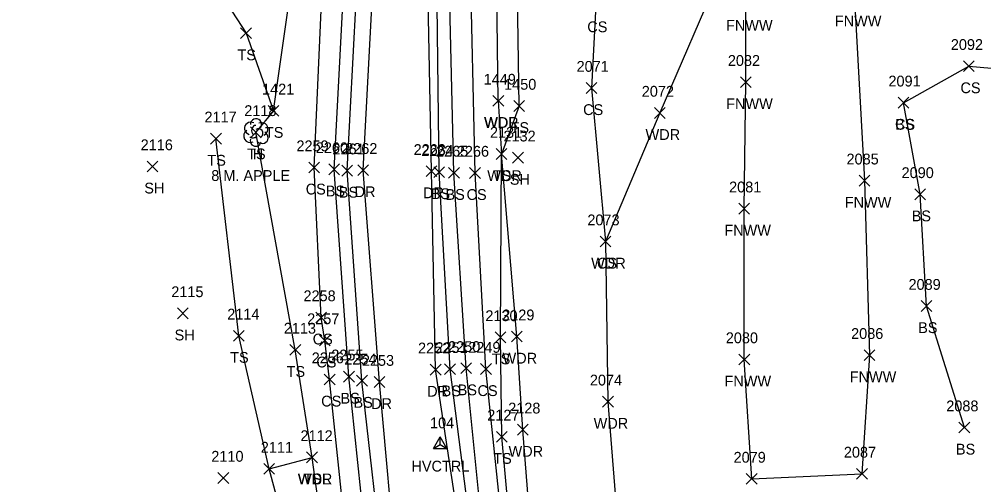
# Model space of a CAD drawing. Extents: x 1761340 to 1763889, y 696770 to 706023.
# Drawn here: x 1761583.4 to 1761761.6, y 700663 to 700749.1 of the extents above; entities that cross this region are included whole.
import ezdxf

# ---------------------------------------------------------------- set-up
doc = ezdxf.new("R2010")
doc.units = 0
for name, color, linetype in [('C_A', 7, 'Continuous'), ('C_I', 7, 'Continuous'), ('CPSM', 7, 'Continuous'), ('L_A', 7, 'Continuous'), ('L_C', 7, 'Continuous'), ('L_I', 7, 'Continuous'), ('L_TIC', 7, 'Continuous'), ('LAWA', 7, 'Continuous'), ('LELB', 7, 'Continuous'), ('LFNC', 7, 'Continuous'), ('LTD', 7, 'Continuous'), ('R_A', 7, 'Continuous'), ('R_I', 7, 'Continuous'), ('R_TIC', 7, 'Continuous'), ('RDP', 7, 'Continuous')]:
    doc.layers.add(name, color=color, linetype=linetype)

msp = doc.modelspace()

# ---------------------------------------------------------------- linework, layer by layer
at = {"layer": 'CPSM'}
for p, q in [((1761659.89, 700669.75), (1761661.14, 700671.91)), ((1761662.39, 700669.75), (1761661.14, 700671.91)), ((1761661.14, 700670.47), (1761661.14, 700671.91)), ((1761659.89, 700669.75), (1761661.14, 700670.47)), ((1761659.89, 700669.75), (1761662.39, 700669.75)), ((1761661.14, 700670.47), (1761661.14, 700670.47)), ((1761661.14, 700670.47), (1761662.39, 700669.75))]:
    msp.add_line(p, q, dxfattribs=at)
at = {"layer": 'L_TIC'}
for points in [[(1761624.27, 700745.55), (1761626.27, 700747.55)], [(1761626.27, 700745.55), (1761624.27, 700747.55)], [(1761757.85, 700739.46), (1761759.85, 700741.46)], [(1761759.85, 700739.46), (1761757.85, 700741.46)], [(1761716.65, 700736.51), (1761718.65, 700738.51)], [(1761718.65, 700736.51), (1761716.65, 700738.51)], [(1761688.12, 700735.42), (1761690.12, 700737.42)], [(1761690.12, 700735.42), (1761688.12, 700737.42)], [(1761670.88, 700733.04), (1761672.88, 700735.04)], [(1761672.88, 700733.04), (1761670.88, 700735.04)], [(1761670.88, 700733.04), (1761672.88, 700735.04)], [(1761672.88, 700733.04), (1761670.88, 700735.04)], [(1761629.34, 700731.21), (1761631.34, 700733.21)], [(1761631.34, 700731.21), (1761629.34, 700733.21)], [(1761674.74, 700732.1), (1761676.74, 700734.1)], [(1761676.74, 700732.1), (1761674.74, 700734.1)], [(1761745.76, 700732.7), (1761747.76, 700734.7)], [(1761747.76, 700732.7), (1761745.76, 700734.7)], [(1761745.76, 700732.7), (1761747.76, 700734.7)], [(1761747.76, 700732.7), (1761745.76, 700734.7)], [(1761700.74, 700730.81), (1761702.74, 700732.81)], [(1761702.74, 700730.81), (1761700.74, 700732.81)], [(1761618.71, 700726.05), (1761620.71, 700728.05)], [(1761620.71, 700726.05), (1761618.71, 700728.05)], [(1761626.06, 700727.23), (1761628.06, 700729.23)], [(1761628.06, 700727.23), (1761626.06, 700729.23)], [(1761671.48, 700723.21), (1761673.48, 700725.21)], [(1761673.48, 700723.21), (1761671.48, 700725.21)], [(1761671.48, 700723.21), (1761673.48, 700725.21)], [(1761673.48, 700723.21), (1761671.48, 700725.21)], [(1761674.53, 700722.53), (1761676.53, 700724.53)], [(1761676.53, 700722.53), (1761674.53, 700724.53)], [(1761606.97, 700720.91), (1761608.97, 700722.91)], [(1761608.97, 700720.91), (1761606.97, 700722.91)], [(1761636.85, 700720.72), (1761638.85, 700722.72)], [(1761638.85, 700720.72), (1761636.85, 700722.72)], [(1761640.56, 700720.37), (1761642.56, 700722.37)], [(1761642.56, 700720.37), (1761640.56, 700722.37)], [(1761642.97, 700720.14), (1761644.97, 700722.14)], [(1761644.97, 700720.14), (1761642.97, 700722.14)], [(1761659.97, 700719.86), (1761661.97, 700721.86)], [(1761661.97, 700719.86), (1761659.97, 700721.86)], [(1761662.69, 700719.73), (1761664.69, 700721.73)], [(1761664.69, 700719.73), (1761662.69, 700721.73)], [(1761666.58, 700719.71), (1761668.58, 700721.71)], [(1761668.58, 700719.71), (1761666.58, 700721.71)], [(1761738.58, 700718.28), (1761740.58, 700720.28)], [(1761740.58, 700718.28), (1761738.58, 700720.28)], [(1761748.84, 700715.76), (1761750.84, 700717.76)], [(1761750.84, 700715.76), (1761748.84, 700717.76)], [(1761716.32, 700713.11), (1761718.32, 700715.11)], [(1761718.32, 700713.11), (1761716.32, 700715.11)], [(1761690.69, 700707.02), (1761692.69, 700709.02)], [(1761692.69, 700707.02), (1761690.69, 700709.02)], [(1761690.69, 700707.02), (1761692.69, 700709.02)], [(1761692.69, 700707.02), (1761690.69, 700709.02)], [(1761612.57, 700693.73), (1761614.57, 700695.73)], [(1761614.57, 700693.73), (1761612.57, 700695.73)], [(1761750.04, 700695.09), (1761752.04, 700697.09)], [(1761752.04, 700695.09), (1761750.04, 700697.09)], [(1761638.14, 700692.98), (1761640.14, 700694.98)], [(1761640.14, 700692.98), (1761638.14, 700694.98)], [(1761622.92, 700689.59), (1761624.92, 700691.59)], [(1761624.92, 700689.59), (1761622.92, 700691.59)], [(1761638.82, 700688.73), (1761640.82, 700690.73)], [(1761640.82, 700688.73), (1761638.82, 700690.73)], [(1761671.28, 700689.3), (1761673.28, 700691.3)], [(1761673.28, 700689.3), (1761671.28, 700691.3)], [(1761674.31, 700689.44), (1761676.31, 700691.44)], [(1761676.31, 700689.44), (1761674.31, 700691.44)], [(1761633.36, 700686.98), (1761635.36, 700688.98)], [(1761635.36, 700686.98), (1761633.36, 700688.98)], [(1761716.35, 700685.21), (1761718.35, 700687.21)], [(1761718.35, 700685.21), (1761716.35, 700687.21)], [(1761739.48, 700686), (1761741.48, 700688)], [(1761741.48, 700686), (1761739.48, 700688)], [(1761661.96, 700683.4), (1761663.96, 700685.4)], [(1761663.96, 700683.4), (1761661.96, 700685.4)], [(1761664.94, 700683.58), (1761666.94, 700685.58)], [(1761666.94, 700683.58), (1761664.94, 700685.58)], [(1761668.6, 700683.44), (1761670.6, 700685.44)], [(1761670.6, 700683.44), (1761668.6, 700685.44)], [(1761639.71, 700681.5), (1761641.71, 700683.5)], [(1761641.71, 700681.5), (1761639.71, 700683.5)], [(1761643.28, 700682.03), (1761645.28, 700684.03)], [(1761645.28, 700682.03), (1761643.28, 700684.03)], [(1761645.69, 700681.27), (1761647.69, 700683.27)], [(1761647.69, 700681.27), (1761645.69, 700683.27)], [(1761691.15, 700677.39), (1761693.15, 700679.39)], [(1761693.15, 700677.39), (1761691.15, 700679.39)], [(1761757.02, 700672.61), (1761759.02, 700674.61)], [(1761759.02, 700672.61), (1761757.02, 700674.61)], [(1761671.54, 700670.9), (1761673.54, 700672.9)], [(1761673.54, 700670.9), (1761671.54, 700672.9)], [(1761675.41, 700672.21), (1761677.41, 700674.21)], [(1761677.41, 700672.21), (1761675.41, 700674.21)], [(1761636.46, 700667.1), (1761638.46, 700669.1)], [(1761638.46, 700667.1), (1761636.46, 700669.1)], [(1761636.46, 700667.1), (1761638.46, 700669.1)], [(1761638.46, 700667.1), (1761636.46, 700669.1)], [(1761636.46, 700667.1), (1761638.46, 700669.1)], [(1761638.46, 700667.1), (1761636.46, 700669.1)], [(1761628.55, 700664.96), (1761630.55, 700666.96)], [(1761630.55, 700664.96), (1761628.55, 700666.96)], [(1761628.55, 700664.96), (1761630.55, 700666.96)], [(1761630.55, 700664.96), (1761628.55, 700666.96)], [(1761738.09, 700664.05), (1761740.09, 700666.05)], [(1761740.09, 700664.05), (1761738.09, 700666.05)], [(1761738.09, 700664.05), (1761740.09, 700666.05)], [(1761740.09, 700664.05), (1761738.09, 700666.05)], [(1761620.06, 700663.29), (1761622.06, 700665.29)], [(1761622.06, 700663.29), (1761620.06, 700665.29)], [(1761717.72, 700663.11), (1761719.72, 700665.11)], [(1761719.72, 700663.11), (1761717.72, 700665.11)], [(1761717.72, 700663.11), (1761719.72, 700665.11)], [(1761719.72, 700663.11), (1761717.72, 700665.11)]]:
    msp.add_lwpolyline(points, dxfattribs=at)
at = {"layer": 'LAWA'}
for points in [[(1761671.88, 700734.04), (1761671.55, 700759.08), (1761673.58, 700793.07), (1761679.61, 700808.98), (1761671.02, 700822.27)], [(1761713.14, 700758.3), (1761701.74, 700731.81), (1761691.69, 700708.02), (1761692.15, 700678.39), (1761694.37, 700650.47), (1761696.35, 700624.4)], [(1761671.88, 700734.04), (1761672.48, 700724.21)], [(1761679.35, 700611.38), (1761679.9, 700629.28), (1761676.41, 700673.21), (1761675.31, 700690.44), (1761672.48, 700724.21)], [(1761637.87, 700635), (1761629.55, 700665.96), (1761637.46, 700668.1)], [(1761637.87, 700635), (1761641.92, 700635.86), (1761637.46, 700668.1)]]:
    msp.add_lwpolyline(points, dxfattribs=at)
at = {"layer": 'LELB'}
for points in [[(1761681.3, 700585.52), (1761671.93, 700613.51), (1761667.59, 700648.27), (1761662.96, 700684.4), (1761660.97, 700720.86), (1761660.49, 700762.08), (1761662.81, 700791.59), (1761666.16, 700822.15), (1761669.09, 700835.75), (1761669.55, 700847.22), (1761671.38, 700859.7), (1761679.65, 700896.38), (1761688.23, 700933.04), (1761696.4, 700960.96), (1761706.35, 700997.91), (1761723.36, 701026.16)], [(1761684.45, 700586.47), (1761674.15, 700613.84), (1761669.56, 700648.24), (1761665.94, 700684.58), (1761663.69, 700720.73), (1761662.67, 700762.27), (1761665.11, 700791.25), (1761666.95, 700822.18), (1761669.97, 700835.61), (1761670.38, 700847.09), (1761671.95, 700859.51), (1761680.67, 700895.81), (1761689.74, 700932.61), (1761697.72, 700961.08), (1761707.94, 700997.33), (1761724.65, 701022.11)], [(1761650.67, 700568.58), (1761653.72, 700589.35), (1761656.23, 700611.85), (1761650.78, 700645.88), (1761646.69, 700682.27), (1761643.97, 700721.14), (1761646.18, 700763.15), (1761649, 700791.97), (1761651.08, 700826.68), (1761655.56, 700862.86), (1761665.44, 700900.35), (1761673.53, 700937.72), (1761682.38, 700964.35), (1761693, 701008.08), (1761690.13, 701015.34), (1761683.01, 701019.11)], [(1761647.36, 700568.69), (1761651.51, 700589.64), (1761652.18, 700611.17), (1761648.15, 700645.92), (1761644.28, 700683.03), (1761641.56, 700721.37), (1761643.75, 700763.66), (1761644.59, 700792.45), (1761648.47, 700827.4), (1761652.74, 700863.51), (1761659.58, 700901.67), (1761670.1, 700938.53), (1761679.51, 700964.49), (1761691.19, 701008.19), (1761682.17, 701016.5)], [(1761650.21, 700590.25), (1761648.81, 700610.46), (1761644.58, 700645.54), (1761640.71, 700682.5), (1761639.82, 700689.73), (1761639.14, 700693.98), (1761637.85, 700721.72), (1761639.72, 700763.34), (1761641.24, 700792.73), (1761643.28, 700816.47), (1761646.04, 700834.75), (1761651.11, 700867.03), (1761649.91, 700870.22), (1761650.05, 700873.46)], [(1761685.1, 700588.24), (1761679.12, 700609.9), (1761673.29, 700649.1), (1761669.6, 700684.44), (1761667.58, 700720.71), (1761666.68, 700761.34), (1761668.83, 700791.97), (1761671.15, 700812.18), (1761668.52, 700820.34)], [(1761675.74, 700733.1), (1761675.38, 700757.77), (1761678.52, 700791.8), (1761684.94, 700802.61)], [(1761583.36, 700790.08), (1761604.19, 700778.98), (1761625.27, 700746.55), (1761630.34, 700732.21)], [(1761630.34, 700732.21), (1761633.5, 700754.29)], [(1761689.89, 700751.74), (1761689.12, 700736.42), (1761691.69, 700708.02)], [(1761746.76, 700733.7), (1761758.85, 700740.46), (1761782.55, 700738.35)], [(1761675.74, 700733.1), (1761672.48, 700724.21)], [(1761758.02, 700673.61), (1761751.04, 700696.09), (1761749.84, 700716.76), (1761746.76, 700733.7)], [(1761630.34, 700732.21), (1761627.06, 700728.23)], [(1761637.46, 700668.1), (1761634.36, 700687.98), (1761627.06, 700728.23)], [(1761629.55, 700665.96), (1761623.92, 700690.59), (1761619.71, 700727.05)], [(1761676.43, 700629.21), (1761672.54, 700671.9), (1761672.28, 700690.3), (1761672.48, 700724.21)]]:
    msp.add_lwpolyline(points, dxfattribs=at)
at = {"layer": 'LFNC'}
for points in [[(1761718.72, 700664.11), (1761717.35, 700686.21), (1761717.32, 700714.11), (1761717.65, 700737.51), (1761717.62, 700752.01), (1761737.74, 700752.83), (1761739.58, 700719.28), (1761740.48, 700687), (1761739.09, 700665.05)], [(1761718.72, 700664.11), (1761739.09, 700665.05)]]:
    msp.add_lwpolyline(points, dxfattribs=at)
at = {"layer": 'LTD'}
msp.add_line((1761627.06, 700728.23), (1761627.06, 700728.23), dxfattribs=at)
msp.add_line((1761627.06, 700728.23), (1761627.06, 700728.23), dxfattribs=at)
msp.add_arc((1761627.11, 700729.66), 1.05, 335.5272, 180.9563, dxfattribs=at)
for centre, major_axis, ratio, start_param, end_param in [((1761626.27, 700728.89), (1.21, -0.51), 0.895232, 1.570796, 4.712389), ((1761626.85, 700728.69), (-0.208, -0.792), 0.645439, 3.141593, 6.283185), ((1761628.1, 700728.81), (-1.14, -0.48), 0.949671, 1.570796, 4.712389), ((1761625.98, 700727.52), (0.58, -1.04), 0.959034, 3.141593, 6.283185), ((1761627.56, 700728.06), (-0.5, 0.667), 0.989748, 3.141593, 6.283185), ((1761628.06, 700727.39), (-1.09, 0.79), 0.841452, 1.570796, 4.712389), ((1761627.06, 700726.73), (0.26, 1.06), 0.942809, 1.570796, 4.712389), ((1761626.61, 700727.48), (-0.625, -0.083), 0.423636, 0, 3.141593)]:
    msp.add_ellipse(centre, major_axis=major_axis, ratio=ratio, start_param=start_param, end_param=end_param, dxfattribs=at)
at = {"layer": 'R_TIC'}
for points in [[(1761645.9, 700720.23), (1761647.9, 700722.23)], [(1761647.9, 700720.23), (1761645.9, 700722.23)], [(1761658.55, 700720.03), (1761660.55, 700722.03)], [(1761660.55, 700720.03), (1761658.55, 700722.03)], [(1761659.31, 700683.32), (1761661.31, 700685.32)], [(1761661.31, 700683.32), (1761659.31, 700685.32)], [(1761648.93, 700681.03), (1761650.93, 700683.03)], [(1761650.93, 700681.03), (1761648.93, 700683.03)]]:
    msp.add_lwpolyline(points, dxfattribs=at)
at = {"layer": 'RDP'}
for points in [[(1761671.26, 700538.43), (1761661.64, 700574.62), (1761657.61, 700611.79), (1761653.18, 700645.74), (1761649.93, 700682.03), (1761646.9, 700721.23), (1761649.1, 700763.06), (1761651.35, 700791.61), (1761653.66, 700826.22), (1761659.48, 700861.88), (1761668.31, 700899.37), (1761676.77, 700936.6), (1761684.87, 700963.93), (1761695.51, 701007.43), (1761695.75, 701009.14), (1761702.96, 701038.72), (1761714.69, 701083.39), (1761730.25, 701133.73)], [(1761685.9, 700541.84), (1761678.4, 700578.09), (1761669.59, 700613.17), (1761665.81, 700647.63), (1761660.31, 700684.32), (1761659.55, 700721.03), (1761658.73, 700762.09), (1761660.8, 700791.69), (1761663.62, 700822.45), (1761666.15, 700836.34), (1761667.52, 700847.08), (1761668.95, 700859.68), (1761676.88, 700896.8), (1761686.16, 700933.2), (1761693.93, 700961.97), (1761704.59, 700998.32), (1761705.06, 700999.04), (1761715.84, 701034.88), (1761727.08, 701077.74), (1761742.29, 701129.68)]]:
    msp.add_lwpolyline(points, dxfattribs=at)

# ---------------------------------------------------------------- texts
at = {"layer": 'C_A'}
msp.add_text('HVCTRL', height=2, dxfattribs=at).set_placement((1761655.83, 700665.47))
at = {"layer": 'C_I'}
msp.add_text('104', height=2, dxfattribs=at).set_placement((1761659.27, 700673.47))
at = {"layer": 'L_A'}
for s, p in [('FNWW', (1761734.09, 700747.83)), ('CS', (1761688.33, 700746.74)), ('FNWW', (1761713.97, 700747.01)), ('TS', (1761623.68, 700741.55)), ('CS', (1761757.3, 700735.46)), ('CS', (1761687.56, 700731.42)), ('FNWW', (1761714, 700732.51)), ('WDR', (1761669.24, 700729.04)), ('WDL', (1761669.3, 700729.04)), ('TS', (1761674.15, 700728.1)), ('CS', (1761745.21, 700728.7)), ('BS', (1761745.21, 700728.7)), ('TS', (1761628.75, 700727.21)), ('WDR', (1761699.1, 700726.81)), ('TS', (1761625.47, 700723.23)), ('H', (1761626.5, 700723.23)), ('TS', (1761618.12, 700722.05)), ('WDR', (1761669.84, 700719.21)), ('TS', (1761670.89, 700719.21)), ('SH', (1761606.46, 700716.91)), ('SH', (1761674.02, 700718.53)), ('CS', (1761636.29, 700716.72)), ('BS', (1761640, 700716.37)), ('BS', (1761642.41, 700716.14)), ('BS', (1761659.41, 700715.86)), ('BS', (1761662.13, 700715.73)), ('CS', (1761666.02, 700715.71)), ('FNWW', (1761735.92, 700714.28)), ('BS', (1761748.28, 700711.76)), ('FNWW', (1761713.66, 700709.11)), ('WDR', (1761689.05, 700703.02)), ('CS', (1761690.13, 700703.02)), ('BS', (1761749.49, 700691.09)), ('SH', (1761612.06, 700689.73)), ('CS', (1761637.58, 700688.98)), ('TS', (1761622.33, 700685.59)), ('CS', (1761638.26, 700684.73)), ('TS', (1761670.69, 700685.3)), ('WDR', (1761672.67, 700685.44)), ('TS', (1761632.77, 700682.98)), ('FNWW', (1761713.7, 700681.21)), ('FNWW', (1761736.83, 700682)), ('BS', (1761661.4, 700679.4)), ('BS', (1761664.38, 700679.58)), ('CS', (1761668.04, 700679.44)), ('BS', (1761642.72, 700678.03)), ('CS', (1761639.15, 700677.5)), ('BS', (1761645.13, 700677.27)), ('WDR', (1761689.51, 700673.39)), ('TS', (1761670.95, 700666.9)), ('WDR', (1761673.78, 700668.21)), ('BS', (1761756.46, 700668.61)), ('WDR', (1761634.82, 700663.1)), ('WDL', (1761634.87, 700663.1)), ('TS', (1761635.87, 700663.1))]:
    msp.add_text(s, height=2, dxfattribs=at).set_placement(p)
at = {"layer": 'L_C'}
msp.add_text('8 M. APPLE', height=2, dxfattribs=at).set_placement((1761618.84, 700719.23))
at = {"layer": 'L_I'}
for s, p in [('2092', (1761755.52, 700743.46)), ('2082', (1761714.31, 700740.51)), ('2071', (1761686.35, 700739.42)), ('1449', (1761669.18, 700737.04)), ('1449', (1761669.18, 700737.04)), ('2091', (1761743.99, 700736.7)), ('2091', (1761743.99, 700736.7)), ('1421', (1761628.22, 700735.21)), ('1450', (1761672.96, 700736.1)), ('2072', (1761698.4, 700734.81)), ('2118', (1761624.94, 700731.23)), ('2118', (1761624.94, 700731.23)), ('2117', (1761617.58, 700730.05)), ('2131', (1761670.35, 700727.21)), ('2131', (1761670.35, 700727.21)), ('2132', (1761672.84, 700726.53)), ('2116', (1761605.79, 700724.91)), ('2259', (1761634.58, 700724.72)), ('2260', (1761638.16, 700724.37)), ('2261', (1761641.23, 700724.14)), ('2264', (1761657.66, 700723.86)), ('2265', (1761660.38, 700723.73)), ('2266', (1761664.22, 700723.71)), ('2085', (1761736.24, 700722.28)), ('2090', (1761746.42, 700719.76)), ('2081', (1761714.54, 700717.11)), ('2073', (1761688.35, 700711.02)), ('2073', (1761688.35, 700711.02)), ('2089', (1761747.7, 700699.09)), ('2115', (1761611.45, 700697.73)), ('2258', (1761635.88, 700696.98)), ('2114', (1761621.79, 700693.59)), ('2257', (1761636.56, 700692.73)), ('2130', (1761669.5, 700693.3)), ('2129', (1761672.61, 700693.44)), ('2113', (1761632.24, 700690.98)), ('2080', (1761713.93, 700689.21)), ('2086', (1761737.09, 700690)), ('2251', (1761660.26, 700687.4)), ('2250', (1761662.6, 700687.58)), ('2249', (1761666.34, 700687.44)), ('2256', (1761637.4, 700685.5)), ('2255', (1761641.02, 700686.03)), ('2254', (1761643.43, 700685.27)), ('2074', (1761688.81, 700681.39)), ('2128', (1761673.72, 700676.21)), ('2088', (1761754.68, 700676.61)), ('2127', (1761669.84, 700674.9)), ('2112', (1761635.33, 700671.1)), ('2112', (1761635.33, 700671.1)), ('2112', (1761635.33, 700671.1)), ('2111', (1761627.99, 700668.96)), ('2111', (1761627.99, 700668.96)), ('2110', (1761618.85, 700667.29)), ('2079', (1761715.37, 700667.11)), ('2079', (1761715.37, 700667.11)), ('2087', (1761735.75, 700668.05)), ('2087', (1761735.75, 700668.05))]:
    msp.add_text(s, height=2, dxfattribs=at).set_placement(p)
at = {"layer": 'R_A'}
for p in [(1761645.33, 700716.23), (1761657.98, 700716.03), (1761658.74, 700679.32), (1761648.37, 700677.03)]:
    msp.add_text('DR', height=2, dxfattribs=at).set_placement(p)
at = {"layer": 'R_I'}
for s, p in [('2262', (1761643.59, 700724.23)), ('2263', (1761656.24, 700724.03)), ('2252', (1761657.05, 700687.32)), ('2253', (1761646.67, 700685.03))]:
    msp.add_text(s, height=2, dxfattribs=at).set_placement(p)

doc.saveas('drawing.dxf')
